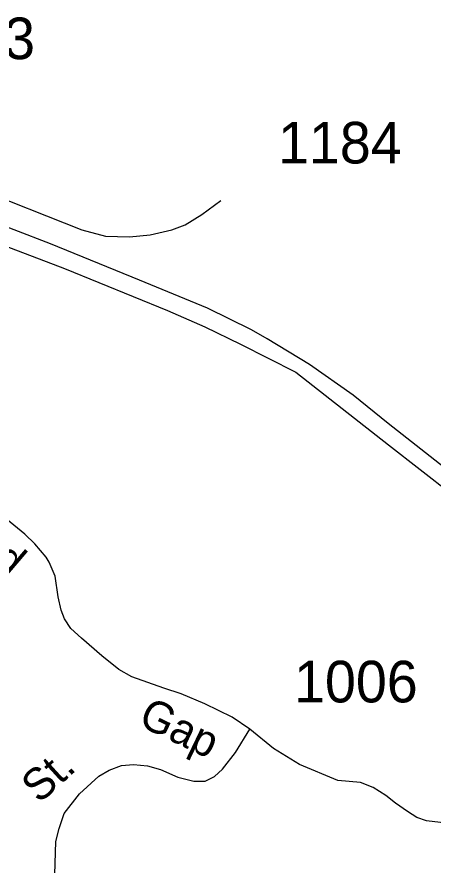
# Model space of a CAD drawing. Extents: x 990631 to 1056237, y 535999 to 585651.
# Drawn here: x 1001128 to 1002378, y 562312 to 564861 of the extents above; entities that cross this region are included whole.
import ezdxf

# ---------------------------------------------------------------- set-up
doc = ezdxf.new("R2010")
doc.units = 0
for name, color, linetype in [('Exist Road Primary Interstate Divided Center Attributed', 7, 'Continuous'), ('Exist Road Secondary Type 41 Attributed', 7, 'Continuous'), ('Exist Road Secondary Type 51 Attributed', 7, 'Continuous'), ('Exist Road Secondary Type 51 Label', 7, 'Continuous'), ('Exist Road Secondary Type 51 Number Label', 7, 'Continuous')]:
    doc.layers.add(name, color=color, linetype=linetype)

msp = doc.modelspace()

# ---------------------------------------------------------------- linework, layer by layer
at = {"layer": 'Exist Road Primary Interstate Divided Center Attributed'}
for points in [[(1000673.1, 564337), (1000749.9, 564308.8), (1000920.2, 564238.4), (1001271.2, 564105.4), (1001580.4, 563979.1), (1001692.8, 563929.9), (1001800, 563877.3), (1001965.6, 563793), (1002244.2, 563575), (1002434.8, 563427.1), (1003174.4, 562824), (1003312.3, 562718.1), (1003716.8, 562414), (1003859.5, 562324.3), (1003995.5, 562246.4), (1004148.2, 562166), (1004338.4, 562081.6), (1004504.5, 562022.7), (1004641.5, 561991), (1004751.7, 561966.5), (1004859.1, 561944.7), (1004942.5, 561926.2), (1005119.3, 561903.4), (1005178.9, 561899.2)], [(1003907.1, 562354.3), (1003798.6, 562416.6), (1003515.9, 562623), (1003162.3, 562899.1), (1002523.2, 563419), (1002243.7, 563638.7), (1002137.6, 563724.4), (1002007, 563817), (1001879.2, 563893.2), (1001832.9, 563920.4), (1001699.9, 563985.7), (1001496.3, 564070.2), (1001229, 564178.9), (1000900.6, 564305.2)]]:
    msp.add_lwpolyline(points, dxfattribs=at)
at = {"layer": 'Exist Road Secondary Type 41 Attributed'}
for points in [[(1001827.4, 562720.1), (1001774.9, 562756.3), (1001692.7, 562796.9), (1001621.4, 562826.6), (1001568.9, 562843.5), (1001472.9, 562878.2), (1001433.5, 562899.6), (1001382.7, 562940.6), (1001321.3, 562994.1), (1001289.6, 563022.8), (1001270.8, 563052.5), (1001260.4, 563077.8), (1001252, 563117.9), (1001242.6, 563180.8), (1001224.8, 563222.4), (1001215.6, 563237.1), (1001181.2, 563277.9), (1001151.5, 563306.7), (1001085.1, 563361.1)], [(1002807.6, 562270.2), (1002776.3, 562315.3), (1002745, 562352.5), (1002696.1, 562393.6), (1002629.5, 562419), (1002551.8, 562443.2), (1002500.3, 562444.2), (1002439.9, 562438.3), (1002400.3, 562440.2), (1002358.7, 562445.2), (1002329, 562455.1), (1002301.3, 562472.9), (1002265.6, 562497.7), (1002235.9, 562521.5), (1002198.3, 562545.3), (1002159.7, 562560.1), (1002092.3, 562566.1), (1001976.9, 562614.1), (1001898.7, 562662.7), (1001827.4, 562720.1)]]:
    msp.add_lwpolyline(points, dxfattribs=at)
at = {"layer": 'Exist Road Secondary Type 51 Attributed'}
for points in [[(1000628.1, 564550.5), (1000688.8, 564521), (1000785.4, 564456.6), (1000906.4, 564388), (1000998.5, 564349.4), (1001322.9, 564221.1), (1001393.6, 564202), (1001465.7, 564200.7), (1001528.3, 564206.1), (1001593.6, 564221.1), (1001633, 564236), (1001683.3, 564267.3), (1001740.4, 564309.5)], [(1001240.9, 562251.1), (1001244.6, 562383.2), (1001254.5, 562422.4), (1001270.2, 562467), (1001315.9, 562526.4), (1001374.3, 562579), (1001405, 562596.8), (1001441.7, 562611.6), (1001478.3, 562614.6), (1001519.9, 562610.7), (1001559.5, 562598.8), (1001611.4, 562575.9), (1001659, 562564.6), (1001693.7, 562564.6), (1001721.4, 562578.5), (1001745.2, 562600.3), (1001784.8, 562650.8), (1001827.4, 562720.1)]]:
    msp.add_lwpolyline(points, dxfattribs=at)

# ---------------------------------------------------------------- texts
at = {"layer": 'Exist Road Secondary Type 51 Label'}
for s, rotation, p in [('Howard', 319.6195, (1000768.9, 563456.3)), ('Howard', 319.6195, (1000768.9, 563456.3)), ('Gap', 334.3529, (1001488.4, 562734.3)), ('Gap', 334.3529, (1001488.4, 562734.3)), ('St.', 42.3968, (1001195.2, 562494.7)), ('St.', 42.3968, (1001195.2, 562494.7))]:
    msp.add_text(s, height=95, rotation=rotation, dxfattribs=at).set_placement(p)
at = {"layer": 'Exist Road Secondary Type 51 Number Label'}
for s, p in [('1183', (1000810.4, 564734.2)), ('1184', (1001912.1, 564420.8)), ('1006', (1001960.3, 562801))]:
    msp.add_text(s, height=125, dxfattribs=at).set_placement(p)

doc.saveas('drawing.dxf')
